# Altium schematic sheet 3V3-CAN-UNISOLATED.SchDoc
size A4; Organization: UNSW Solar Racing Team; Address3: UNSW; Address4: Sydney NSW 2052; Address2: Electrical Engineering; Address1: Rm 109
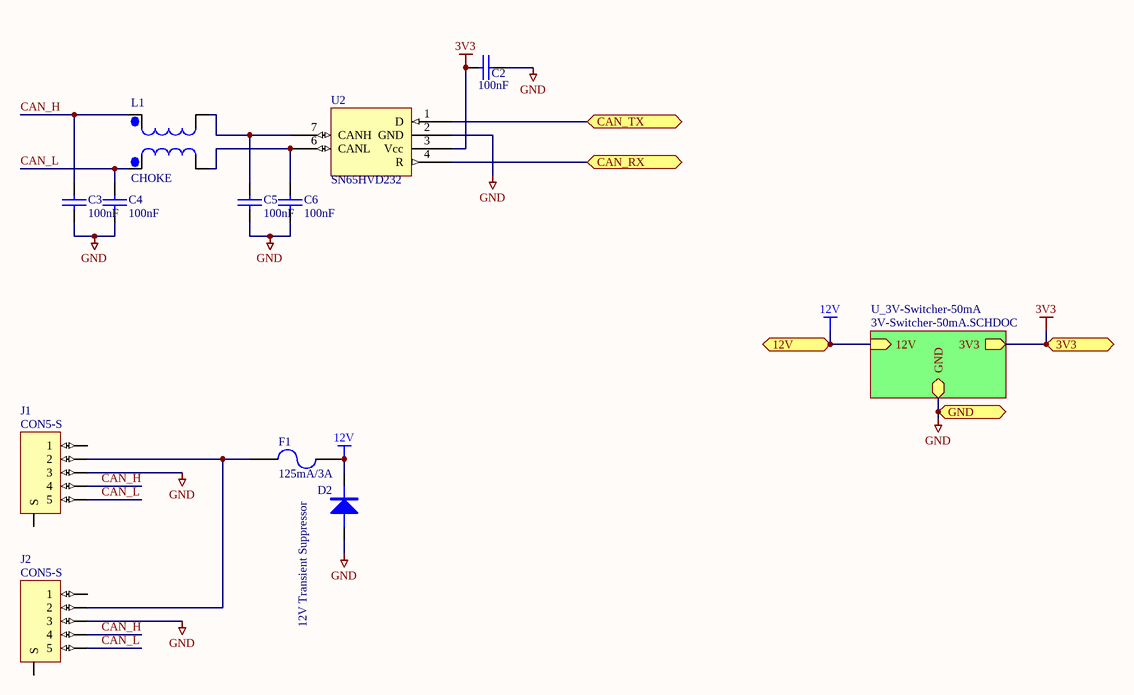
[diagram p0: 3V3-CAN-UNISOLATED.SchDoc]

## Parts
C2  100nF  [0603]
C3  100nF  [0603]
C4  100nF  [0603]
C5  100nF  [0603]
C6  100nF  [0603]
D2  12V Transient Suppressor  [SMA]
F1  125mA/3A  [LITTELFUSE-154]
J1  CON5-S  [TRIAD5F]
J2  CON5-S  [TRIAD5F]
L1  CHOKE  [Epcos-Choke]
U2  SN65HVD232  [SO8]

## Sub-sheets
U_3V-Switcher-50mA = 3V-Switcher-50mA.SCHDOC: GND, 3V3, 12V

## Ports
3V3, 12V, CAN_RX, CAN_TX, GND

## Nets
3V3: C2.2 U2.3(Vcc) ; port 3V3, sheet U_3V-Switcher-50mA/3V3
12V: D2.K F1.2 ; port 12V, sheet U_3V-Switcher-50mA/12V
GND: C2.1 C3.1 C4.2 C5.2 C6.2 D2.A J1.3 J2.3 U2.2(GND) ; port GND, sheet U_3V-Switcher-50mA/GND
CAN_H: C3.2 J1.4 J2.4 L1.1
CAN_L: C4.1 J1.5 J2.5 L1.2
CAN_RX: U2.4(R) ; port CAN_RX
CAN_TX: U2.1(D) ; port CAN_TX
NetC5_1: C5.1 L1.4 U2.7(CANH)
NetC6_1: C6.1 L1.3 U2.6(CANL)
NetF1_1: F1.1 J1.2 J2.2

Not connected (* = marked no-connect by the designer): J1 0(S) 1; J2 0(S) 1

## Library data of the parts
C2-C6 = CAP: Capacitor; Order#: 753-567
D2 = DIODE: Order#: 980-2754
F1 = FUSE2: Fuse; Order#: 994-3609
J1 J2 = CON5-S: Connector, 2 pin, with shield @ S; Order#: 131-040
U2 = SN65HVD232: 3.3V CAN Transciever; Order#: 296-12282-5-ND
